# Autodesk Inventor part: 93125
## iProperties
Author: Administrator
Shininess: 64.0
Angle Display Precision: 2
Document Length Units: 11272
Document Angle Units: 11286
Document Time Units: 11279
Document Mass Units: 11290
Document Length Units Precision: 3
Document Angle Units Precision: 2
Compacted: True
PropertySet Name: _Private Model Information
Created: 2002-03
Part Number: 93125
Material: ASTM A36 HRS
Document SubType Name: Modeling
Designer: Administrator
Control State: 0
Master: False
Checked Out: False
PropertySet Name: Design Tracking Control
Density: 0.0
Volumn: 0.0
Area: 0.0
PropertySet Name: Model Information
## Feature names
1. Revolution1
